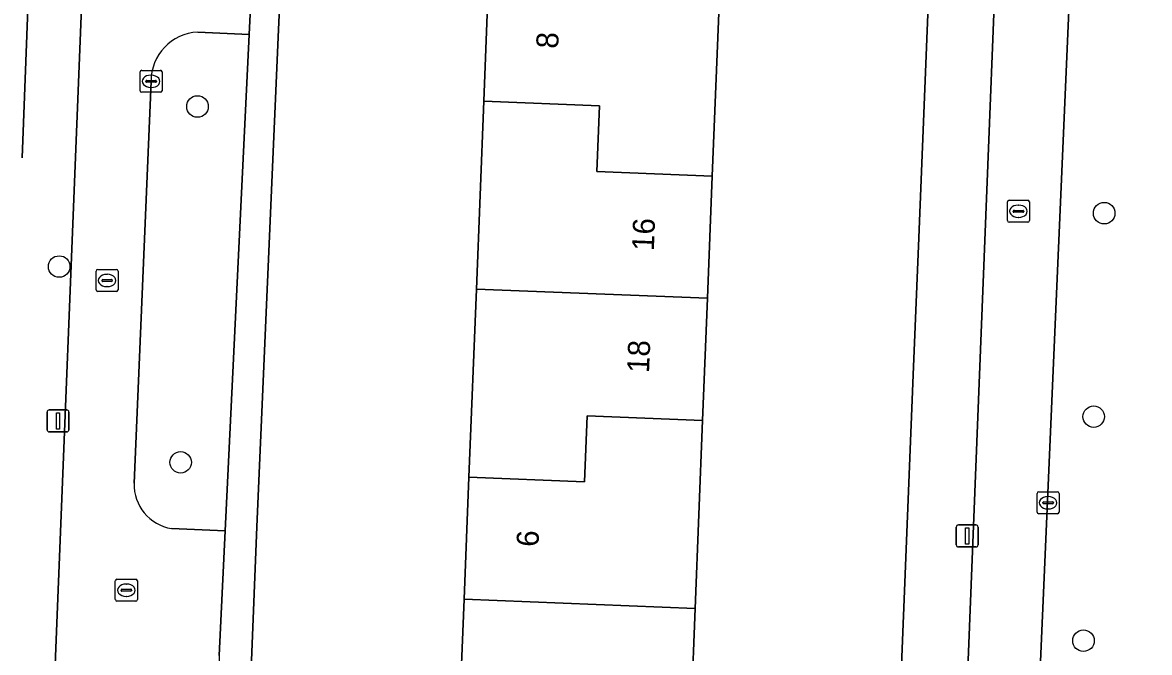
# Model space of a CAD drawing. Extents: x 160786 to 161429, y 386828 to 387485.
# Drawn here: x 161232.7 to 161283.9, y 387134.4 to 387163.1 of the extents above; entities that cross this region are included whole.
import ezdxf

# ---------------------------------------------------------------- set-up
doc = ezdxf.new("R2010")
doc.units = 0
for name, color, linetype in [('IMGEO_Boom', 7, 'Continuous'), ('IMGEO_Erf', 7, 'Continuous'), ('IMGEO_Groenvoorziening', 7, 'Continuous'), ('IMGEO_Kolk', 7, 'Continuous'), ('IMGEO_Lichtmast', 7, 'Continuous'), ('IMGEO_Muur', 7, 'Continuous'), ('IMGEO_Pand', 7, 'Continuous'), ('IMGEO_Pand_nummerreeks', 7, 'Continuous'), ('IMGEO_Rijbaan_lokaal_open', 7, 'Continuous'), ('IMGEO_Rioolput', 7, 'Continuous'), ('IMGEO_Voetpad_open', 7, 'Continuous')]:
    doc.layers.add(name, color=color, linetype=linetype)

msp = doc.modelspace()

# ---------------------------------------------------------------- linework, layer by layer
at = {"layer": 'IMGEO_Boom'}
for centre in [(161240.653, 387159.264), (161281.863, 387154.413), (161234.367, 387151.985), (161281.387, 387145.16), (161239.887, 387143.079), (161280.921, 387134.968)]:
    msp.add_circle(centre, 0.489, dxfattribs=at)
at = {"layer": 'IMGEO_Erf'}
for points in [[(161253.33, 387150.958), (161253.667, 387159.508), (161253.887, 387165.061), (161254.106, 387170.614), (161254.45, 387179.314), (161244.996, 387179.611), (161244.674, 387170.837), (161244.589, 387168.523), (161244.314, 387162.41), (161243.357, 387140.152), (161243.104, 387134.077), (161242.148, 387112.001), (161242.03, 387108.866), (161248.226, 387108.633), (161251.652, 387108.504), (161251.877, 387114.202), (161252.215, 387122.752), (161252.553, 387131.302), (161252.772, 387136.855), (161252.992, 387142.408)], [(161273.183, 387147.065), (161273.433, 387153.29), (161274.312, 387175.172), (161274.445, 387178.506), (161273.131, 387178.559), (161268.3, 387178.753), (161264.952, 387178.899), (161264.727, 387173.196), (161264.389, 387164.646), (161264.051, 387156.096), (161263.832, 387150.543), (161263.612, 387144.99), (161263.274, 387136.44), (161262.936, 387127.89), (161262.717, 387122.337), (161262.498, 387116.784), (161262.154, 387108.089), (161271.604, 387107.738), (161272.052, 387118.888), (161272.304, 387125.162)]]:
    msp.add_lwpolyline(points, close=True, dxfattribs=at)
at = {"layer": 'IMGEO_Groenvoorziening'}
msp.add_lwpolyline([(161299.307, 387176.427), (161299.252, 387176.525), (161299.125, 387176.709), (161298.982, 387176.882), (161298.824, 387177.04), (161298.653, 387177.184), (161298.469, 387177.313), (161298.275, 387177.424), (161298.072, 387177.518), (161297.861, 387177.593), (161297.644, 387177.648), (161297.423, 387177.685), (161297.2, 387177.701), (161297.141, 387177.702), (161296.822, 387177.713), (161296.78, 387176.514), (161295.847, 387176.547), (161295.888, 387177.746), (161280.89, 387178.267), (161277.95, 387110.686), (161296.512, 387109.859)], close=True, dxfattribs=at)
for points in [[(161232.68, 387156.934), (161233.342, 387174.08)], [(161239.479, 387140.07), (161241.914, 387139.969), (161243.004, 387162.534)], [(161243.004, 387162.534), (161240.667, 387162.651)], [(161238.545, 387160.405), (161237.775, 387142.135)]]:
    msp.add_lwpolyline(points, dxfattribs=at)
for centre, radius, start, end in [((161240.775, 387160.423), 2.23, 92.7792, 180.473), ((161239.799, 387142.07), 2.025, 178.1586, 260.899)]:
    msp.add_arc(centre, radius, start, end, dxfattribs=at)
at = {"layer": 'IMGEO_Kolk'}
for p, q in [((161238.043, 387159.983), (161238.043, 387160.835)), ((161238.118, 387160.909), (161238.97, 387160.909)), ((161239.044, 387160.835), (161239.044, 387159.983)), ((161238.302, 387160.403), (161238.302, 387160.415)), ((161238.74, 387160.366), (161238.342, 387160.366)), ((161238.345, 387160.452), (161238.743, 387160.452)), ((161238.531, 387160.689), (161238.556, 387160.689)), ((161238.786, 387160.415), (161238.786, 387160.403)), ((161238.97, 387159.909), (161238.118, 387159.909)), ((161238.554, 387160.129), (161238.529, 387160.129)), ((161278.812, 387140.818), (161278.812, 387141.67)), ((161278.887, 387141.744), (161279.739, 387141.744)), ((161279.3, 387141.524), (161279.325, 387141.524)), ((161279.813, 387141.67), (161279.813, 387140.818)), ((161279.071, 387141.238), (161279.071, 387141.25)), ((161279.509, 387141.201), (161279.111, 387141.201)), ((161279.114, 387141.287), (161279.512, 387141.287)), ((161279.323, 387140.964), (161279.298, 387140.964)), ((161279.555, 387141.25), (161279.555, 387141.238)), ((161279.739, 387140.744), (161278.887, 387140.744)), ((161236.994, 387137.766), (161237.846, 387137.766)), ((161236.919, 387136.84), (161236.919, 387137.692)), ((161237.178, 387137.26), (161237.178, 387137.272)), ((161237.616, 387137.223), (161237.218, 387137.223)), ((161237.221, 387137.309), (161237.619, 387137.309)), ((161237.407, 387137.546), (161237.432, 387137.546)), ((161237.662, 387137.272), (161237.662, 387137.26)), ((161237.92, 387137.692), (161237.92, 387136.84)), ((161237.846, 387136.766), (161236.994, 387136.766)), ((161237.43, 387136.986), (161237.405, 387136.986))]:
    msp.add_line(p, q, dxfattribs=at)
for points in [[(161238.043, 387159.983), (161238.043, 387160.835)], [(161238.118, 387160.909), (161238.97, 387160.909)], [(161239.044, 387160.835), (161239.044, 387159.983)], [(161238.97, 387159.909), (161238.118, 387159.909)], [(161278.812, 387140.818), (161278.812, 387141.67)], [(161278.887, 387141.744), (161279.739, 387141.744)], [(161279.813, 387141.67), (161279.813, 387140.818)], [(161279.739, 387140.744), (161278.887, 387140.744)], [(161236.994, 387137.766), (161237.846, 387137.766)], [(161236.919, 387136.84), (161236.919, 387137.692)], [(161237.92, 387137.692), (161237.92, 387136.84)], [(161237.846, 387136.766), (161236.994, 387136.766)]]:
    msp.add_lwpolyline(points, dxfattribs=at)
for centre, radius, start, end in [((161238.12, 387160.833), 0.0765, 91.552, 178.448), ((161238.12, 387160.833), 0.0765, 91.552, 178.448), ((161238.968, 387160.833), 0.0765, 1.552, 88.448), ((161238.968, 387160.833), 0.0765, 1.552, 88.448), ((161238.342, 387160.412), 0.0403, 85.8775, 175.7526), ((161238.339, 387160.402), 0.0366, 178.938, 274.7102), ((161238.743, 387160.409), 0.043, 264.8664, 352.4533), ((161238.747, 387160.414), 0.0386, 1.7309, 96.639), ((161238.12, 387159.985), 0.0765, 181.552, 268.448), ((161238.12, 387159.985), 0.0765, 181.552, 268.448), ((161238.968, 387159.985), 0.0765, 271.552, 358.448), ((161238.968, 387159.985), 0.0765, 271.552, 358.448), ((161278.889, 387141.668), 0.0765, 91.552, 178.448), ((161278.889, 387141.668), 0.0765, 91.552, 178.448), ((161279.737, 387141.668), 0.0765, 1.552, 88.448), ((161279.737, 387141.668), 0.0765, 1.552, 88.448), ((161278.889, 387140.82), 0.0765, 181.552, 268.448), ((161278.889, 387140.82), 0.0765, 181.552, 268.448), ((161279.111, 387141.247), 0.0403, 85.8775, 175.7526), ((161279.108, 387141.237), 0.0366, 178.938, 274.7102), ((161279.512, 387141.244), 0.043, 264.8664, 352.4533), ((161279.516, 387141.249), 0.0386, 1.7309, 96.639), ((161279.737, 387140.82), 0.0765, 271.552, 358.448), ((161279.737, 387140.82), 0.0765, 271.552, 358.448), ((161236.996, 387137.69), 0.0765, 91.552, 178.448), ((161236.996, 387137.69), 0.0765, 91.552, 178.448), ((161237.844, 387137.69), 0.0765, 1.552, 88.448), ((161237.844, 387137.69), 0.0765, 1.552, 88.448), ((161237.218, 387137.269), 0.0403, 85.8775, 175.7526), ((161237.215, 387137.259), 0.0366, 178.938, 274.7102), ((161237.619, 387137.266), 0.043, 264.8664, 352.4533), ((161237.623, 387137.271), 0.0386, 1.7309, 96.639), ((161236.996, 387136.842), 0.0765, 181.552, 268.448), ((161236.996, 387136.842), 0.0765, 181.552, 268.448), ((161237.844, 387136.842), 0.0765, 271.552, 358.448), ((161237.844, 387136.842), 0.0765, 271.552, 358.448)]:
    msp.add_arc(centre, radius, start, end, dxfattribs=at)
for centre, major_axis, ratio, start_param, end_param in [((161238.53, 387160.409), (-0.387, 0.002), 0.722429, 4.712389, 7.853982), ((161238.555, 387160.409), (-0.39, 0.002), 0.717154, 1.570796, 4.712389), ((161279.299, 387141.244), (-0.387, 0.002), 0.722429, 4.712389, 7.853982), ((161279.324, 387141.244), (-0.39, 0.002), 0.717154, 1.570796, 4.712389), ((161237.406, 387137.266), (-0.387, 0.002), 0.722429, 4.712389, 7.853982), ((161237.431, 387137.266), (-0.39, 0.002), 0.717154, 1.570796, 4.712389)]:
    msp.add_ellipse(centre, major_axis=major_axis, ratio=ratio, start_param=start_param, end_param=end_param, dxfattribs=at)
at = {"layer": 'IMGEO_Lichtmast'}
for p, q in [((161233.919, 387145.465), (161234.709, 387145.465)), ((161234.709, 387145.465), (161233.919, 387145.465)), ((161233.819, 387144.565), (161233.819, 387145.365)), ((161233.819, 387145.365), (161233.819, 387144.565)), ((161234.809, 387145.365), (161234.809, 387144.565)), ((161234.809, 387144.565), (161234.809, 387145.365)), ((161234.709, 387144.465), (161233.919, 387144.465)), ((161233.919, 387144.465), (161234.709, 387144.465)), ((161275.138, 387139.332), (161275.138, 387140.132)), ((161275.138, 387140.132), (161275.138, 387139.332)), ((161275.238, 387140.232), (161276.028, 387140.232)), ((161276.028, 387140.232), (161275.238, 387140.232)), ((161276.128, 387140.132), (161276.128, 387139.332)), ((161276.128, 387139.332), (161276.128, 387140.132)), ((161276.028, 387139.232), (161275.238, 387139.232)), ((161275.238, 387139.232), (161276.028, 387139.232))]:
    msp.add_line(p, q, dxfattribs=at)
for points in [[(161234.239, 387145.34), (161234.389, 387145.34), (161234.389, 387144.59), (161234.239, 387144.59), (161234.239, 387145.34)], [(161275.558, 387140.107), (161275.708, 387140.107), (161275.708, 387139.357), (161275.558, 387139.357), (161275.558, 387140.107)]]:
    msp.add_lwpolyline(points, dxfattribs=at)
for centre, start, end in [((161233.919, 387145.365), 90, 180), ((161233.919, 387145.365), 90, 180), ((161234.709, 387145.365), 0, 90), ((161234.709, 387145.365), 360, 90), ((161233.919, 387144.565), 180, 270), ((161233.919, 387144.565), 180, 270), ((161234.709, 387144.565), 270, 0), ((161234.709, 387144.565), 270, 0), ((161275.238, 387140.132), 90, 180), ((161275.238, 387140.132), 90, 180), ((161276.028, 387140.132), 0, 90), ((161276.028, 387140.132), 360, 90), ((161275.238, 387139.332), 180, 270), ((161275.238, 387139.332), 180, 270), ((161276.028, 387139.332), 270, 0), ((161276.028, 387139.332), 270, 0)]:
    msp.add_arc(centre, 0.1, start, end, dxfattribs=at)
at = {"layer": 'IMGEO_Muur'}
for points in [[(161274.312, 387175.172), (161273.433, 387153.29)], [(161244.314, 387162.41), (161243.357, 387140.152)], [(161273.183, 387147.065), (161272.304, 387125.162)]]:
    msp.add_lwpolyline(points, dxfattribs=at)
at = {"layer": 'IMGEO_Pand'}
for points in [[(161253.887, 387165.061), (161253.667, 387159.508), (161258.918, 387159.3), (161258.8, 387156.303), (161264.051, 387156.096), (161264.389, 387164.646)], [(161263.832, 387150.543), (161264.051, 387156.096), (161258.8, 387156.303), (161258.918, 387159.3), (161253.667, 387159.508), (161253.33, 387150.958)], [(161253.33, 387150.958), (161252.992, 387142.408), (161258.243, 387142.2), (161258.361, 387145.197), (161263.612, 387144.99), (161263.832, 387150.543)], [(161263.274, 387136.44), (161263.612, 387144.99), (161258.361, 387145.197), (161258.243, 387142.2), (161252.992, 387142.408), (161252.772, 387136.855)], [(161252.772, 387136.855), (161252.553, 387131.302), (161257.805, 387131.094), (161257.687, 387128.097), (161262.936, 387127.89), (161263.274, 387136.44)]]:
    msp.add_lwpolyline(points, close=True, dxfattribs=at)
at = {"layer": 'IMGEO_Rijbaan_lokaal_open'}
msp.add_lwpolyline([(161280.89, 387178.267), (161277.439, 387178.387), (161274.45, 387103.153), (161277.618, 387103.057), (161277.95, 387110.686)], close=True, dxfattribs=at)
for points in [[(161238.965, 387171.006), (161239.091, 387173.88), (161237.598, 387173.932), (161235.791, 387173.995), (161233.72, 387122.137)], [(161240.667, 387162.651), (161243.004, 387162.534), (161243.287, 387168.391), (161240.771, 387168.461)], [(161237.775, 387142.135), (161238.545, 387160.405)], [(161241.914, 387139.969), (161239.479, 387140.07)], [(161241.64, 387134.292), (161241.914, 387139.969)]]:
    msp.add_lwpolyline(points, dxfattribs=at)
for centre, radius, start, end in [((161240.775, 387160.423), 2.23, 92.7792, 180.473), ((161239.799, 387142.07), 2.025, 178.1586, 260.899)]:
    msp.add_arc(centre, radius, start, end, dxfattribs=at)
at = {"layer": 'IMGEO_Rioolput'}
for p, q in [((161277.462, 387154.073), (161277.462, 387154.925)), ((161277.537, 387154.999), (161278.389, 387154.999)), ((161277.95, 387154.779), (161277.975, 387154.779)), ((161278.463, 387154.925), (161278.463, 387154.073)), ((161277.721, 387154.493), (161277.721, 387154.505)), ((161278.159, 387154.456), (161277.761, 387154.456)), ((161277.764, 387154.542), (161278.162, 387154.542)), ((161277.973, 387154.219), (161277.948, 387154.219)), ((161278.205, 387154.505), (161278.205, 387154.493)), ((161278.389, 387153.999), (161277.537, 387153.999)), ((161236.043, 387150.926), (161236.043, 387151.778)), ((161236.118, 387151.852), (161236.97, 387151.852)), ((161236.531, 387151.632), (161236.556, 387151.632)), ((161237.044, 387151.778), (161237.044, 387150.926)), ((161236.302, 387151.346), (161236.302, 387151.358)), ((161236.74, 387151.309), (161236.342, 387151.309)), ((161236.345, 387151.395), (161236.743, 387151.395)), ((161236.554, 387151.072), (161236.529, 387151.072)), ((161236.786, 387151.358), (161236.786, 387151.346)), ((161236.97, 387150.852), (161236.118, 387150.852))]:
    msp.add_line(p, q, dxfattribs=at)
for points in [[(161277.462, 387154.073), (161277.462, 387154.925)], [(161277.537, 387154.999), (161278.389, 387154.999)], [(161278.463, 387154.925), (161278.463, 387154.073)], [(161278.389, 387153.999), (161277.537, 387153.999)], [(161236.043, 387150.926), (161236.043, 387151.778)], [(161236.118, 387151.852), (161236.97, 387151.852)], [(161237.044, 387151.778), (161237.044, 387150.926)], [(161236.97, 387150.852), (161236.118, 387150.852)]]:
    msp.add_lwpolyline(points, dxfattribs=at)
for centre, radius, start, end in [((161277.539, 387154.923), 0.0765, 91.552, 178.448), ((161277.539, 387154.923), 0.0765, 91.552, 178.448), ((161278.387, 387154.923), 0.0765, 1.552, 88.448), ((161278.387, 387154.923), 0.0765, 1.552, 88.448), ((161277.761, 387154.502), 0.0403, 85.8775, 175.7526), ((161277.758, 387154.492), 0.0366, 178.938, 274.7102), ((161278.162, 387154.499), 0.043, 264.8664, 352.4533), ((161278.166, 387154.504), 0.0386, 1.7309, 96.639), ((161277.539, 387154.075), 0.0765, 181.552, 268.448), ((161277.539, 387154.075), 0.0765, 181.552, 268.448), ((161278.387, 387154.075), 0.0765, 271.552, 358.448), ((161278.387, 387154.075), 0.0765, 271.552, 358.448), ((161236.12, 387151.776), 0.0765, 91.552, 178.448), ((161236.12, 387151.776), 0.0765, 91.552, 178.448), ((161236.968, 387151.776), 0.0765, 1.552, 88.448), ((161236.968, 387151.776), 0.0765, 1.552, 88.448), ((161236.342, 387151.355), 0.0403, 85.8775, 175.7526), ((161236.339, 387151.345), 0.0366, 178.938, 274.7102), ((161236.743, 387151.352), 0.043, 264.8664, 352.4533), ((161236.747, 387151.357), 0.0386, 1.7309, 96.639), ((161236.12, 387150.928), 0.0765, 181.552, 268.448), ((161236.12, 387150.928), 0.0765, 181.552, 268.448), ((161236.968, 387150.928), 0.0765, 271.552, 358.448), ((161236.968, 387150.928), 0.0765, 271.552, 358.448)]:
    msp.add_arc(centre, radius, start, end, dxfattribs=at)
for centre, major_axis, ratio, start_param, end_param in [((161277.949, 387154.499), (-0.387, 0.002), 0.722429, 4.712389, 7.853982), ((161277.974, 387154.499), (-0.39, 0.002), 0.717154, 1.570796, 4.712389), ((161236.53, 387151.352), (-0.387, 0.002), 0.722429, 4.712389, 7.853982), ((161236.555, 387151.352), (-0.39, 0.002), 0.717154, 1.570796, 4.712389)]:
    msp.add_ellipse(centre, major_axis=major_axis, ratio=ratio, start_param=start_param, end_param=end_param, dxfattribs=at)
at = {"layer": 'IMGEO_Voetpad_open'}
for points in [[(161244.314, 387162.41), (161244.589, 387168.523), (161244.674, 387170.837), (161244.996, 387179.611), (161243.823, 387179.482), (161243.287, 387168.391), (161243.004, 387162.534), (161241.914, 387139.969), (161241.64, 387134.292), (161241.633, 387134.148), (161241.632, 387134.125), (161240.766, 387111.847), (161240.664, 387109.128), (161240.488, 387104.436), (161240.741, 387104.427), (161241.911, 387104.405), (161242.03, 387108.866), (161242.148, 387112.001), (161243.104, 387134.077), (161243.357, 387140.152)], [(161277.439, 387178.387), (161274.445, 387178.506), (161274.312, 387175.172), (161273.433, 387153.29), (161273.183, 387147.065), (161272.304, 387125.162), (161272.052, 387118.888), (161271.604, 387107.738), (161271.425, 387103.275), (161274.45, 387103.153)]]:
    msp.add_lwpolyline(points, close=True, dxfattribs=at)
msp.add_lwpolyline([(161230.818, 387122.202), (161233.72, 387122.137), (161235.791, 387173.995), (161233.342, 387174.08), (161232.68, 387156.934)], dxfattribs=at)

# ---------------------------------------------------------------- texts
at = {"layer": 'IMGEO_Pand_nummerreeks'}
for s, rotation, p in [('8', 87.7372, (161257.044, 387161.884)), ('16', 87.7366, (161261.394, 387152.685)), ('18', 87.7366, (161261.175, 387147.135)), ('6', 87.7372, (161256.149, 387139.227))]:
    msp.add_text(s, height=1, rotation=rotation, dxfattribs=at).set_placement(p)

doc.saveas('drawing.dxf')
